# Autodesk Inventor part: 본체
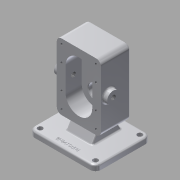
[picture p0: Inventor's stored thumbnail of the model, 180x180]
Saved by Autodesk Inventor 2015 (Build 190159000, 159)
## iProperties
Created: 2020-04
Part Number: 본체
Material: 알루미늄 6061
Document SubType Name: Modeling
Designer: CAD02
Density: 2.7 g/cm^3
Appearance: 알루미늄 - 평지
Mass: 1468.95 g
Surface Area: 831.041 cm^2
Volume: 544.054 cm^3
Author: CAD02
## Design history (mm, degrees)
sketch "스케치4"
  geometry: L1 (-24, 44.641)-(24, 44.641) reference; L2 (24, 44.641)-(24, 10) reference; L3 (24, 10)-(60, 10) reference; L4 (60, 10)-(60, 0) reference; L5 (60, 0)-(-60, 0) reference; L6 (-60, 0)-(-60, 10) reference; L7 (-60, 10)-(-24, 10) reference; L8 (-24, 10)-(-24, 44.641) reference; L9 (40, 150)-(-40, 150); L10 (-40, 150)-(-40, 30); L11 (-40, 30)-(40, 30); L12 (40, 30)-(40, 150); 3 further points
  constraints: 8 end point, 2 midpoint, 2 parallel, 1 horizontal, 1 perpendicular, 1 vertical alignment
  dimensions: "d19" = 150 distance between parallel lines of L5 L9; "d20" = 120 distance of L11.end L9.start; "d21" = 80 distance of L9.start L9.end
extrude "돌출3" join sketch "스케치4" stored distance "d22" = 53; taper "d23" = 0 deg
sketch "스케치5"
  geometry: L1 (0, 112)-(0, 68); L2 (24, 112)-(24, 68); L3 (-24, 68)-(-24, 112); L4 (-50, 0)-(50, 0) reference; A1 r 24 centre (0, 112) between (24, 112) and (-24, 112); A2 r 24 centre (0, 68) between (-24, 68) and (24, 68); 2 further points
  constraints: 8 end point, 4 point on circle, 4 tangent, 2 centre point, 1 midpoint, 1 parallel, 1 vertical
  dimensions: "d24" = 92 dimension on A2 A1; "d25" = 44 distance of L1.end L1.start; "d26" = 90 distance from line of L4 point (0, 90)
extrude "돌출4" cut sketch "스케치5" distance "d27" = 29; taper "d28" = 0 deg
sketch "스케치6"
  geometry: C1 r 12.5 at (0, 112); C2 r 12.5 at (0, 68); A1 r 24 centre (0, 112) between (24, 112) and (-24, 112) reference; A2 r 24 centre (0, 68) between (-24, 68) and (24, 68) reference; 1 further point
  constraints: 2 centre point, 2 coincident
  dimensions: "d29" = 25 diameter of C1; "d30" = 25 diameter of C2
extrude "돌출5" cut sketch "스케치6" distance "d31" = 15; taper "d32" = 0 deg
sketch "스케치7"
  geometry: C1 r 19 at (0, -112); A1 r 24 centre (0, -112) between (-24, -112) and (24, -112) reference; 1 further point
  constraints: 1 centre point, 1 coincident
  dimensions: "d33" = 38 diameter of C1
extrude "돌출6" join sketch "스케치7" distance "d34" = 17; taper "d35" = 0 deg
sketch "스케치8"
  geometry: C1 r 19 at (0, 0) reference; C2 r 14 at (0, 0); 1 further point
  constraints: 1 centre point, 1 coincident
  dimensions: "d36" = 28 diameter of C2
extrude "돌출7" cut sketch "스케치8" distance "d37" = 7.3; taper "d38" = 0 deg
sketch "스케치9"
  geometry: C1 r 14 at (0, 0) reference; C2 r 8.5 at (0, 0); 1 further point
  constraints: 1 centre point, 1 coincident
  dimensions: "d39" = 17 diameter of C2
extrude "돌출8" cut sketch "스케치9" stored distance "d40" = 7.3; taper "d41" = 0 deg
chamfer "모따기1" distance "d42" = 0.7; stored, may be unused: second distance "d43" = 2, angle "d44" = 30 deg
fillet "모깎기2" dims "d45" = 0.5
node "작업 평면3"
sketch "스케치11"
  geometry: L1 (-40, 30)-(40, 30) reference; L2 (-31, 141)-(31, 141); L3 (31, 141)-(31, 39); L4 (31, 39)-(-31, 39); L5 (-31, 39)-(-31, 141); L6 (-40, 150)-(40, 150) reference; L7 (0, 150)-(0, 30); L8 (-31, 112)-(31, 112); L9 (-31, 90)-(31, 90); L10 (-31, 68)-(31, 68); L11 (40, 150)-(-40, 150) reference; 12 further points
  constraints: 16 end point, 8 coincident, 7 midpoint, 4 horizontal, 4 point on line, 2 parallel, 1 horizontal alignment, 1 perpendicular, 1 vertical alignment
  dimensions: "d54" = 62 distance of L2.start L2.end; "d55" = 102 distance of L4.end L2.start; "d56" = 29 distance between parallel lines of L8 L2; "d57" = 44 distance between parallel lines of L10 L8
hole "구멍2" sketch "스케치11" at (-31, 141), (-31, 112), (-31, 68), (-31, 39), (31, 39), (31, 68), (31, 112), (31, 141) diameter "d58" = 4.134; stored, may be unused: countersink angle "d62" = 90 deg, drill point angle "d64" = 118 deg; dims "d59" = 10, "d60" = 4, "d61" = 2, "d63" = 12
chamfer "모따기2" distance "d65" = 1; stored, may be unused: second distance "d66" = 2, angle "d67" = 30 deg
fillet "모깎기7" dims "d68" = 3
fillet "모깎기9" dims "d70" = 9
fillet "모깎기10" dims "d71" = 3
sketch "스케치12"
  geometry: L1 (102, 0)-(0, 0) reference; C1 r 11 at (51, 14); 1 further point
  constraints: 1 centre point
  dimensions: "d72" = 22 diameter of C1; "d73" = 14 distance from line of L1 C1.centre
extrude "돌출9" join sketch "스케치12" distance "d74" = 8; taper "d75" = 0 deg
fillet "모깎기11" dims "d76" = 3
sketch "스케치13"
  geometry: L1 (102, 0)-(0, 0) reference; C1 r 11 at (51, 14); 1 further point
  constraints: 1 centre point
  dimensions: "d77" = 22 diameter of C1; "d78" = 14 distance from line of L1 C1.centre
extrude "돌출10" join sketch "스케치13" distance "d79" = 8; taper "d80" = 0 deg
fillet "모깎기12" dims "d81" = 3
sketch "스케치14"
  geometry: C1 r 11 at (0, 0) reference; 1 further point
hole "구멍3" sketch "스케치14" at (0, 0) diameter "d82" = 8.376; stored, may be unused: countersink angle "d86" = 90 deg, drill point angle "d88" = 118 deg; dims "d83" = 20, "d84" = 4, "d85" = 2, "d87" = 27.3
sketch "스케치15"
  geometry: C1 r 11 at (0, 0) reference; 1 further point
hole "구멍4" sketch "스케치15" at (0, 0) diameter "d89" = 8.376; stored, may be unused: countersink angle "d93" = 90 deg, drill point angle "d95" = 118 deg; dims "d90" = 20, "d91" = 4, "d92" = 2, "d94" = 27.3
node "작업 평면4"
sketch "스케치16"
  geometry: L1 (91, -30)-(-29, -30); L2 (-29, -30)-(-29, 70); L3 (-29, 70)-(91, 70); L4 (91, 70)-(91, -30); L5 (91, -30)-(-29, 70); L6 (-29, -30)-(91, 70); L7 (50, 70)-(12, 70) reference; 3 further points
  constraints: 12 end point, 4 midpoint, 2 parallel, 1 horizontal, 1 perpendicular, 1 vertical alignment
  dimensions: "d97" = 120 distance of L2.end L3.end; "d98" = 100 distance of L1.end L2.end
extrude "돌출11" join sketch "스케치16" distance "d99" = 10; taper "d100" = 0 deg
sketch "스케치17"
  geometry: L1 (-29, -30)-(91, -30) reference; L2 (91, 70)-(-29, 70) reference; L3 (55, 0)-(7, 0); L4 (7, 0)-(7, 53); L5 (7, 53)-(55, 53); L6 (55, 53)-(55, 0); L7 (55, 0)-(7, 53); L8 (7, 0)-(55, 53); 4 further points
  constraints: 12 end point, 4 midpoint, 2 parallel, 1 horizontal, 1 perpendicular, 1 vertical alignment
  dimensions: "d101" = 48 distance of L3.start L3.end; "d102" = 53 distance of L5.end L3.start; "d103" = 17 distance between parallel lines of L5 L2
extrude "돌출12" new body sketch "스케치17" distance "d104" = 30; taper "d105" = 0 deg
feature "면 기울기3" dims angle "d106" = 30 deg
feature "결합1"
  node "솔리드2"
fillet "모깎기13" dims "d107" = 10
fillet "모깎기14" dims "d108" = 3
sketch "스케치18"
  geometry: A1 r 7 centre (-19, 60) between (-19, 67) and (-26, 60) reference; A2 r 7 centre (-19, -20) between (-26, -20) and (-19, -27) reference; A3 r 7 centre (81, -20) between (81, -27) and (88, -20) reference; A4 r 7 centre (81, 60) between (88, 60) and (81, 67) reference; 1 further point
hole "구멍5" sketch "스케치18" at (81, 60), (-19, 60), (-19, -20), (81, -20) diameter "d109" = 9; stored, may be unused: countersink angle "d113" = 90 deg, drill point angle "d115" = 118 deg; dims "d110" = 20, "d111" = 4, "d112" = 2, "d114" = 27.3
sketch "스케치19"
  geometry: L1 (-29, 60)-(-29, -20) reference; L2 (-19, -30)-(81, -30) reference; 2 further points
  constraints: 1 other
  dimensions: "d116" = 60 distance from line of L1 point (31, -20); "d117" = 10 distance from line of L2 point (31, -20)
feature "엠보싱2" sketch "스케치19" dims "d118" = 0.5, "d119" = 0
fillet "모깎기15" dims "d120" = 3
fillet "모깎기16" dims "d121" = 3
node "솔리드1"
mirror "대칭1"
node "절단 모서리 투영1"
